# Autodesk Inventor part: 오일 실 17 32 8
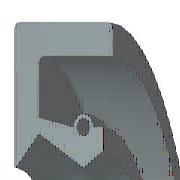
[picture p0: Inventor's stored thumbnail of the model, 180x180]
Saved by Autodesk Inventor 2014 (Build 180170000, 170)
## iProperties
IsCustomPart: 0
Created: 2018-09
Part Number: 오일 실 17 32 8
Material: 고무
Description: 오일-실
Document SubType Name: Modeling
Standard: KS B 2804
Standards Organization: KS
Language: ko-KR
Size Designation: D - 17 32 8
Categories: <MemberInstance><Categories><Category DisplayName="샤프트 부품" InternalName="7f7aeb1f-a693-4053-b835-cee3144e0d98" Mnemonic="SHFT"><Category DisplayName="실링" Intern
Density: 0.93 g/cm^3
Appearance: 고무 - 검은색 - 버전 1.1
Mass: 2.28027 g
Surface Area: 32.1224 cm^2
Volume: 2.45191 cm^3
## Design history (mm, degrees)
revolve "본체" stored, may be unused: angle "d17" = 90 deg
revolve "스프링1" stored, may be unused: angle "d18" = 90 deg
body "Solid1"
sketch "스케치1"
  geometry: L1 (0, 16)-(8, 16); L2 (8, 14.25)-(1.75, 14.25); L3 (1.75, 10.25)-(4.9, 8.5); L4 (4.9, 8.5)-(0, 8.5); L5 (0, 0)-(9.586, 0) reference; L6 (4.9, 8.5)-(6.3, 9.375); L7 (0, 18)-(0, -3) reference; L8 (-1.941, 0)-(11.507, 0) reference; L9 (4.2, 10.6)-(1.75, 11.21); L10 (1.75, 11.21)-(1.75, 14.25); L11 (0, 16)-(0, 8.588); L12 (4.9, 8.5)-(0, 8.5); L13 (1.75, 10.25)-(0.152, 8.528); L14 (8, 16)-(8, 14.25); L15 (5.6, 10.6)-(6.3, 10.6); L16 (6.3, 10.6)-(6.3, 9.375); C1 r 0.455 at (4.9, 10.6); A1 r 0.7 centre (4.9, 10.6) between (5.6, 10.6) and (4.2, 10.6); A2 r 0.088 centre (0.088, 8.588) between (0, 8.588) and (0.152, 8.528); 1 further point
  constraints: 28 end point, 5 horizontal alignment, 5 point on line, 4 point on circle, 4 vertical alignment, 3 centre point, 3 tangent, 2 collinear, 2 horizontal, 2 perpendicular, 1 coincident, 1 parallel
  dimensions: "d0" = 32 diameter of L1 L5 (= SD2); "d1" = 1.75 distance of L1.end L2.start (= SD); "d2" = 0.91 diameter of C1 (= SPDI); "d3" = 1.4 diameter of A1 (= SPDA); "d4" = 17 diameter of L3.end L5 (= NND); "d5" = 20.5 diameter of L3.start L5 (= TKDM); "d7" = 22.42 diameter of L9.end L5 (= TKDM + 0.24 x SWDT); "d8" = 1.75 distance between parallel lines of L11 L10 (= SD); "d9" = 4.9 distance from line of L11 C1.centre (= SPDST); "d10" = 21.2 diameter of C1.centre L5 (= HLDM); "d11" = 0.0875 radius of A2 (= 0.25 x LAB); "d12" = 6.3 distance between parallel lines of L11 L16 (= SDI); "d13" = 18.75 diameter of L6.end L5 (= ABDM); "d14" = 8 distance from line of L11 L1.end (= SWDT)
fillet "모깎기1" dims "d6" = 0.3 (= RR)
other parameters: "SD2" = 32 [user parameter; used in 1 equation term], "SWDT" = 8 [user parameter; used in 2 equation terms], "RR" = 0.3 [user parameter; used in 1 equation term], "SD" = 1.75 [user parameter; used in 2 equation terms], "NND" = 17 [user parameter; used in 1 equation term], "SPDA" = 1.4 [user parameter; used in 1 equation term], "SPDI" = 0.91 [user parameter; used in 1 equation term], "TKDM" = 20.5 [user parameter; used in 2 equation terms], "HLDM" = 21.2 [user parameter; used in 1 equation term], "ABDM" = 18.75 [user parameter; used in 1 equation term], "SDI" = 6.3 [user parameter; used in 1 equation term], "SPDST" = 4.9 [user parameter; used in 1 equation term], "LAB" = 0.35 [user parameter; used in 1 equation term], "d15" = 0, "d16" = 0, "d19" = 0
